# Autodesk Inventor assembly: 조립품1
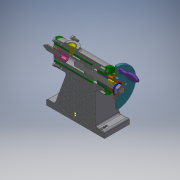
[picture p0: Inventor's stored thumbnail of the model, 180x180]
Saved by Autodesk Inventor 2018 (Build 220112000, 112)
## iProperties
Created: 2019-10
Part Number: 조립품1
Document SubType Name: Assembly
Designer: Administrator
Author: Administrator
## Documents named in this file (18)
- C:\Users\Administrator\Desktop\조립품1.iam
- C:\Users\Administrator\Desktop\본체.ipt
- C:\Users\Administrator\Documents\491004V1017\슬리브.ipt
- C:\Users\Administrator\Documents\491004V1017\중공축.ipt
- C:\Users\Administrator\Documents\491004V1017\센터홀더.ipt
- C:\Users\Administrator\Documents\491004V1017\멈춤나사 M3.ipt
- C:\Users\Administrator\Documents\491004V1017\센터.ipt
- C:\Users\Administrator\Documents\491004V1017\커버.ipt
- C:\Users\Administrator\Documents\491004V1017\부시.ipt
- C:\Users\Administrator\Documents\491004V1017\나사축.ipt
- C:\Users\Administrator\Documents\491004V1017\키 4 x 4 x 10.ipt
- C:\Users\Administrator\Documents\491004V1017\플랜지.ipt
- C:\Users\Administrator\Documents\491004V1017\돌림판.ipt
- C:\Users\Administrator\Documents\491004V1017\와셔.ipt
- C:\Users\Administrator\Documents\491004V1017\너트 M8.ipt
- C:\Users\Administrator\Documents\491004V1017\핸들.ipt
- C:\Users\Administrator\Documents\491004V1017\나사.ipt
- C:\Users\Administrator\Documents\491004V1017\볼트 M3.ipt
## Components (2 placed, 2 different names)
1. 플랜지:1
2. 핸들:1 — 플러쉬:9
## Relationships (1: Flush 1)
- 플러쉬:9 [Flush]: 핸들:1
